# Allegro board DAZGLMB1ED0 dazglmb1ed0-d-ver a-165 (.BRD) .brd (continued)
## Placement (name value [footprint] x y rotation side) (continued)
CN2078  P_TP@196195-10021  [196195-10021-10P-L]  137.5 50.53 0 top
CN2079  Tobii@50228-0067N-001  [87212-0600-6P-L]  31.6 85 90 top
D11  SDM20U30-7  [D-1_2X0_8-0_7H]  174.52 61.43 0 bottom
D13  *SDM20U30-7  [D-1_2X0_8-0_7H]  174.52 62.83 0 bottom
D15  *SDM20U30-7  [D-1_2X0_8-0_7H]  174.52 60.04 0 bottom
D17  *SDM20U30-7  [D-1_2X0_8-0_7H]  174.52 65.62 0 bottom
D18  *SDM20U30-7  [D-1_2X0_8-0_7H]  174.52 64.23 0 bottom
D19  RB500V-40  [DSM]  175.75 64.86 270 top
D51  AZ5725-01F.R7G  [ESD-1X0_6-2P]  369.46 37.81 180 top
D73  *RB500V-40  [DSM]  342.29 64.61 90 top
D8553  *AZ5725-01F.R7G  [ESD-1X0_6-2P]  352.6 78.2 270 top
D8554  *AZ5725-01F.R7G  [ESD-1X0_6-2P]  353.61 78.2 270 top
D8555  *AZ5725-01F.R7G  [ESD-1X0_6-2P]  351.58 78.2 270 top
D8556  *AZ5725-01F.R7G  [ESD-1X0_6-2P]  350.57 78.2 270 top
D8557  SDM20U30-7  [D-1_2X0_8-0_7H]  348.51 90.26 90 bottom
D8558  *AZ5725-01F.R7G  [ESD-1X0_6-2P]  234.97 167.35 90 top
D8559  BAT54AW-L  [SOT323_213-2_1-1_3-3P]  228.37 165.57 90 top
D8565  *P_PB@AZ5725-01F.R7G  [ESD-1X0_6-2P]  172.87 58.64 90 top
D8566  *M_KB@AZ5725-01F.R7G  [ESD-1X0_6-2P]  127.53 53.94 270 bottom
D8567  *M_KB@AZ5725-01F.R7G  [ESD-1X0_6-2P]  127.53 55.97 90 bottom
D8568  BAT54CW  [UMT_213-3-1_3]  45.87 72.48 90 top
D8569  AZ5725-01F.R7G  [ESD-1X0_6-2P]  15.26 16.6 90 top
D8570  AZ5725-01F.R7G  [ESD-1X0_6-2P]  14.6 7.66 270 top
D8571  AZ5725-01F.R7G  [ESD-1X0_6-2P]  15.18 9.74 270 top
D8575  AZ5725-01F.R7G  [ESD-1X0_6-2P]  15.77 20.54 270 top
D8576  AZ5725-01F.R7G  [ESD-1X0_6-2P]  18.21 21.78 270 top
D8577  AZ5725-01F.R7G  [ESD-1X0_6-2P]  22.09 26.94 90 top
D8586  *RB500V-40  [DSM]  37.49 53.43 180 top
D8587  RB500V-40  [DSM]  37.49 51.53 180 top
D8588  SDM20U30-7  [D-1_2X0_8-0_7H]  135.28 119.6 180 bottom
D8589  RB500V-40  [DSM]  134.64 121.38 0 top
D8591  SDM20U30-7  [D-1_2X0_8-0_7H]  119.78 117.06 180 bottom
D8592  SDM20U30-7  [D-1_2X0_8-0_7H]  115.84 118.58 0 bottom
D8594  60@SDM20U30-7  [D-1_2X0_8-0_7H]  119.78 118.58 0 bottom
D8595  BAT54AW-L  [SOT323_213-2_1-1_3-3P]  122.83 119.35 0 top
D8596  AZ5725-01F.R7G  [ESD-1X0_6-2P]  25.67 73.96 270 top
D8597  AZ5725-01F.R7G  [ESD-1X0_6-2P]  25.67 75.96 90 top
D8598  AZ5725-01F.R7G  [ESD-1X0_6-2P]  17.93 36.54 180 top
D8599  PESD5V0H1BSF  [D-0_6X0_3-0_32H-SMT]  373.07 40.82 90 top
D13025  PESD5V0H1BSF  [D-0_6X0_3-0_32H-SMT]  367.75 47.65 270 bottom
D13026  PESD5V0H1BSF  [D-0_6X0_3-0_32H-SMT]  373.07 40.82 90 bottom
D13027  PESD5V0H1BSF  [D-0_6X0_3-0_32H-SMT]  367.75 47.65 270 top
D13028  PESD5V0H1BSF  [D-0_6X0_3-0_32H-SMT]  367.75 46.03 90 bottom
D13029  PESD5V0H1BSF  [D-0_6X0_3-0_32H-SMT]  373.07 42.44 270 top
D13030  PESD5V0H1BSF  [D-0_6X0_3-0_32H-SMT]  367.75 46.03 90 top
D13031  PESD5V0H1BSF  [D-0_6X0_3-0_32H-SMT]  373.07 42.44 270 bottom
D13032  PESD5V0H1BSF  [D-0_6X0_3-0_32H-SMT]  376.96 38.83 90 bottom
D13033  PESD5V0H1BSF  [D-0_6X0_3-0_32H-SMT]  378.1 38.83 90 bottom
D13034  PESD5V0H1BSF  [D-0_6X0_3-0_32H-SMT]  377.34 42.76 0 bottom
D13035  PESD5V0H1BSF  [D-0_6X0_3-0_32H-SMT]  382.8 43.91 180 bottom
D13036  PESD5V0H1BSF  [D-0_6X0_3-0_32H-SMT]  372.38 38.83 90 bottom
D13037  PESD5V0H1BSF  [D-0_6X0_3-0_32H-SMT]  373.53 38.83 90 bottom
D13038  RB500V-40  [DSM]  17.17 33.37 90 top
D13039  RB500V-40  [DSM]  18.94 33.37 90 top
D13040  *AZ5725-01F.R7G  [ESD-1X0_6-2P]  349.52 78.2 270 top
D13041  *AZ5725-01F.R7G  [ESD-1X0_6-2P]  348.48 78.17 270 top
D13042  *M_PB@AZ5725-01F.R7G  [ESD-1X0_6-2P]  377.01 15.79 90 bottom
D13046  *AZ5725-01F.R7G  [ESD-1X0_6-2P]  377.64 19.12 270 bottom
D13047  *AZ5725-01F.R7G  [ESD-1X0_6-2P]  375.81 19.52 0 bottom
D13048  *AZ5725-01F.R7G  [ESD-1X0_6-2P]  378.66 19.12 270 bottom
D13049  *AZ5725-01F.R7G  [ESD-1X0_6-2P]  369.59 21.43 270 bottom
D13050  *AZ5725-01F.R7G  [ESD-1X0_6-2P]  371.5 21.17 270 bottom
D13051  *AZ5725-01F.R7G  [ESD-1X0_6-2P]  372.51 21.17 270 bottom
D13053  *M_PB@AZ5725-01F.R7G  [ESD-1X0_6-2P]  379.7 10.56 270 top
D13054  *P_PB@AZ5725-01F.R7G  [ESD-1X0_6-2P]  180.5 48.93 180 top
D13055  *P_PB@AZ5725-01F.R7G  [ESD-1X0_6-2P]  181.03 46.6 180 top
D13056  *P_PB@AZ5725-01F.R7G  [ESD-1X0_6-2P]  180.52 47.74 180 top
D13057  *AZ5725-01F.R7G  [ESD-1X0_6-2P]  84.42 77.11 270 bottom
D13058  *AZ5725-01F.R7G  [ESD-1X0_6-2P]  86.76 77.11 270 bottom
D13059  *AZ5725-01F.R7G  [ESD-1X0_6-2P]  85.59 77.11 270 bottom
D13060  PESD5V0H1BSF  [D-0_6X0_3-0_32H-SMT]  375.81 38.83 90 bottom
D13061  PESD5V0H1BSF  [D-0_6X0_3-0_32H-SMT]  374.67 38.83 90 bottom
D13064  *Tobii@AZ5725-01F.R7G  [ESD-1X0_6-2P]  29.1 79.85 180 top
D13065  *Tobii@AZ5725-01F.R7G  [ESD-1X0_6-2P]  31.01 79.85 0 top
D13066  SUB@RB500V-40  [DSM]  37.49 49.7 180 top
D13067  *SUB@RB500V-40  [DSM]  37.49 47.9 180 top
D13069  RB500V-40  [DSM]  206.54 103.5 90 top
D13070  *RB500V-40  [DSM]  359.63 40.28 0 top
D13071  Debug@PESD5V0H1BSF  [D-0_6X0_3-0_32H-SMT]  217.95 170.15 270 top
D13072  Debug@PESD5V0H1BSF  [D-0_6X0_3-0_32H-SMT]  219.1 170.15 270 top
D13073  Debug@PESD5V0H1BSF  [D-0_6X0_3-0_32H-SMT]  220.24 170.15 270 top
D13074  Debug@PESD5V0H1BSF  [D-0_6X0_3-0_32H-SMT]  221.51 170.15 270 top
D13075  Debug@PESD5V0H1BSF  [D-0_6X0_3-0_32H-SMT]  222.91 170.15 270 top
D13076  Debug@PESD5V0H1BSF  [D-0_6X0_3-0_32H-SMT]  224.18 170.15 270 top
D13077  Debug@PESD5V0H1BSF  [D-0_6X0_3-0_32H-SMT]  225.42 170.15 270 top
D13078  Debug@PESD5V0H1BSF  [D-0_6X0_3-0_32H-SMT]  226.46 170.15 270 top
D13079  Debug@PESD5V0H1BSF  [D-0_6X0_3-0_32H-SMT]  240.56 169.26 270 top
D13080  Debug@PESD5V0H1BSF  [D-0_6X0_3-0_32H-SMT]  241.7 169.26 270 top
D13081  Debug@PESD5V0H1BSF  [D-0_6X0_3-0_32H-SMT]  243.25 169.26 270 top
D13082  Debug@PESD5V0H1BSF  [D-0_6X0_3-0_32H-SMT]  244.37 169.26 270 top
D13083  Debug@PESD5V0H1BSF  [D-0_6X0_3-0_32H-SMT]  245.61 169.23 270 top
D13084  Debug@PESD5V0H1BSF  [D-0_6X0_3-0_32H-SMT]  246.78 169.26 270 top
D13085  Debug@PESD5V0H1BSF  [D-0_6X0_3-0_32H-SMT]  247.82 169.26 270 top
D13086  Debug@PESD5V0H1BSF  [D-0_6X0_3-0_32H-SMT]  248.94 169.26 270 top
D13087  AZ5725-01F.R7G  [ESD-1X0_6-2P]  182.8 67.58 90 bottom
D13088  *SDM20U30-7  [D-1_2X0_8-0_7H]  124.73 108.8 0 bottom
D13089  SDM20U30-7  [D-1_2X0_8-0_7H]  14.41 29.15 270 bottom
D13090  SDM20U30-7  [D-1_2X0_8-0_7H]  16.06 22.19 270 bottom
D13094  AZ5725-01F.R7G  [ESD-1X0_6-2P]  24.51 80.23 270 top
D13095  *SDM20U30-7  [D-1_2X0_8-0_7H]  129.89 111.98 90 top
ESD7  Debug@AZ1045-04F.R7G  [UDFN10-2_5X1-5-9P]  229.13 169.89 180 top
ESD8  Debug@AZ1045-04F.R7G  [UDFN10-2_5X1-5-9P]  251.61 167.1 0 top
HOLE1  MBZ8P00301  [H-C197D126P2]  26.93 65 0 top
HOLE2  *H-C315D177P2  [H-C315D177P2]  100.84 92.19 0 top
HOLE3  *H-C315D126P2  [H-C315D126P2]  5 92.5 0 top
HOLE4  *H-C315D177P2  [H-C315D177P2]  19.5 57 0 top
HOLE5  *H-C315D177P2  [H-C315D177P2]  53 25.89 0 top
HOLE6  *H-C315D126P2  [H-C315D126P2]  200.5 61 0 top
HOLE7  *H-C315D126P2  [H-C315D126P2]  382 92.5 0 top
HOLE8  *H-C315D177P2  [H-C315D177P2]  210.5 176.5 0 top
HOLE9  *H-C315D118P2  [H-C315D118P2]  382 0.5 0 top
HOLE10  *H-C315D118P2  [H-C315D118P2]  5 0.5 0 top
HOLE11  *H-C315D162P2  [H-C315D162P2]  374 49 0 top
HOLE12  *H-C315D177P2  [H-C315D177P2]  288.64 91.82 0 top
HOLE13  *H-C315D126P2  [H-C315D126P2]  261.5 178 0 top
HOLE14  *H-TBC315IC126D126P2  [H-TBC315IC126D126P2]  119 178 0 top
HOLE15  *H-O152X112D152X112N  [H-O152X112D152X112N]  11.99 92.5 0 top
HOLE16  *H-TIC197BC315D150P2  [H-TIC197BC315D150P2]  184.58 104.73 0 top
HOLE17  *H-TIC197BC315D150P2  [H-TIC197BC315D150P2]  217.98 106.87 0 top
HOLE18  *H-TIC197BC315D150P2  [H-TIC197BC315D150P2]  161.11 159.05 0 top
HOLE19  *H-TIC197BC315D150P2  [H-TIC197BC315D150P2]  137.64 104.73 0 top
HOLE20  *H-TIC197BC315D150P2  [H-TIC197BC315D150P2]  217.98 131.59 0 top
HOLE21  *H-TIC197BC315D150P2  [H-TIC197BC315D150P2]  271.98 119.23 0 top
HOLE22  *H-O152X112D152X112N  [H-O152X112D152X112N]  11.52 3.5 0 top
JP1  *solderjumper-2  [SOLDERJUMPER-2]  325.27 51.4 180 top
JP10  *short3720  [SHORT3720]  98.83 76.24 0 top
L12  0.68uH_2.5x2.0x1.2  [L2_5X2-PHT25201T-R47MS]  355.34 62.2 90 top
L13  BLM15AG121SN1D  [R0402]  190.85 56.94 180 bottom
L14  BLM15AG121SN1D  [R0402]  190.82 58.28 180 bottom
L4234  SUB@0_5%_6  [R0603]  38.02 41.01 90 bottom
L4235  SUB@0_5%_6  [R0603]  39.69 42.28 90 bottom
L4236  SUB@0_5%_6  [R0603]  28.32 37.48 180 top
L4237  SUB@0_5%_6  [R0603]  28.34 39.31 180 top
L4238  BLM15AG121SN1D  [R0402]  179.85 69.94 270 top
L4240  PBY160808T-600Y-N  [R0603]  32.51 25.77 270 top
L4241  HCB2012KF-220T60  [R0805]  20.98 33.24 90 top
L4242  4.7uH_3.2x2.5x2  [L3_2X2_5-3_2]  344.19 69.56 0 top
L4243  HCB1608KF-601T10  [R0603]  345.46 71.97 0 top
L4244  HCB1608KF-601T10  [R0603]  342.79 71.97 0 top
L4245  PBY160808T-600Y-N  [R0603]  163.6 102.71 0 top
L4246  PBY160808T-600Y-N  [R0603]  153.18 105.76 270 bottom
L4247  *MCM2012B900GBE  [FILTER-MCM2012B900GBE-4P]  21.18 39.72 0 top
L4248  *MCM2012B900GBE  [FILTER-MCM2012B900GBE-4P]  21.36 37.43 0 top
L4249  *MCM2012B900GBE  [FILTER-MCM2012B900GBE-4P]  21.36 42 0 top
L4250  BLM15PX330SN1D  [R0402]  30.12 56.18 0 top
L4251  *MCM2012B900GBE  [FILTER-MCM2012B900GBE-4P]  21.36 48.73 0 top
L4252  *MCM2012B900GBE  [FILTER-MCM2012B900GBE-4P]  21.36 46.57 0 top
L4253  *MCM2012B900GBE  [FILTER-MCM2012B900GBE-4P]  21.36 50.89 0 top
L4254  *MCM2012B900GBE  [FILTER-MCM2012B900GBE-4P]  28.09 74.9 0 top
L4255  *MCM2012B900GBE  [FILTER-MCM2012B900GBE-4P]  366.42 59.4 180 top
L4256  *MCM2012B900GBE  [FILTER-MCM2012B900GBE-4P]  366.42 61.43 180 top
L4257  *MCM2012B900GBE  [FILTER-MCM2012B900GBE-4P]  366.42 57.37 180 top
L4258  PBY160808T-600Y-N  [R0603]  330.22 62.6 90 top
L4259  *PBY160808T-600Y-N  [R0603]  331.69 62.6 90 top
L4264  *PBY160808T-600Y-N  [R0603]  334.28 62.96 0 top
L4266  1uH_0.7A_0603  [R0603]  338.73 48.73 0 top
L4268  DIS@BLM15PX330SN1D  [R0402]  331.67 68.29 90 bottom
L4269  PBY160808T-600Y-N  [R0603]  37.87 31.72 270 top
L4270  BLM15PX330SN1D  [R0402]  30.75 30.88 270 bottom
L4271  *BLM15PX330SN1D  [R0402]  24.18 19.12 0 bottom
L4272  SUB@HCB2012KF-220T60  [R0805]  28.44 42.61 270 top
L4273  BLM15PX330SN1D  [R0402]  23.66 36.03 0 bottom
LED1  R/G/B_LTST-C19JZRGBW-Q  [LEDLTST-C19JZRGBW-Q-4P]  376.5 33.75 0 top
LED2  R/G/B_LTST-C19JZRGBW-Q  [LEDLTST-C19JZRGBW-Q-4P]  376.5 23.36 0 top
MR1  YB8251ST23  [SOT23_213-3_3-2]  235.5 162 90 top
NOREF  -  []  282.98 14.44 0 top
NOREF#2  -  [unnamed#2]  235.7 171.77 0 top
NOREF#3  -  []  19.53 91.15 0 top
NOREF#4  -  []  97.05 -1.81 0 top
NOREF#5  -  []  196.35 47.42 0 top
NOREF#6  -  [unnamed#2]  381.09 6.61 0 top
NOREF#7  -  [unnamed#2]  12.29 88.48 0 top
NOREF#8  -  []  113.86 94.64 180 bottom
NOREF#9  -  []  200.48 47.67 180 bottom
NOREF#10  -  [unnamed#2]  18.21 92.15 180 bottom
NOREF#11  -  [unnamed#2]  235.82 171.68 180 bottom
NOREF#12  -  [unnamed#2]  381.09 6.61 180 bottom
PC1  1000p/50V_4  [C0402]  207.79 169.33 90 bottom
PC2  0.047u/50V_6  [C0603]  209.06 168.88 270 bottom
PC3  0.1u/25V_4  [C0402]  73.91 61.26 180 bottom
PC4  0.1u/25V_4  [C0402]  72.28 61.92 90 bottom
PC5  0.1u/50V_6  [C0603]  192.68 167.22 0 top
PC6  0.1u/25V_4  [C0402]  73.91 62.22 180 bottom
PC7  2200p/50V_4  [C0402]  216.12 170.73 180 top
PC8  0.01u/50V_4  [C0402]  75.2 59.33 180 bottom
PC9  2.2u/10V_4  [C0402]  76.22 57.09 180 bottom
PC10  *47p/50V_4  [C0402]  152.39 57.75 180 bottom
PC11  *47p/50V_4  [C0402]  154.2 57.75 0 bottom
PC12  0.1u/50V_6  [C0603]  214.55 171.44 270 top
PC13  2200p/50V_4  [C0402]  190.9 171.29 0 top
PC14  0.1u/50V_6  [C0603]  189.89 172.56 0 top
PC15  0.047u/50V_4  [C0402]  76.6 54.32 180 bottom
PC16  0.47u/25V_4  [C0402]  76.6 52.8 180 bottom
PC17  *0.01u/50V_4  [C0402]  70.73 61.38 180 bottom
PC18  *100p/50V_4  [C0402]  65.4 53.41 270 bottom
PC19  *680p/50V_6  [C0603]  79.65 59.02 0 bottom
PC20  100p/50V_4  [C0402]  65.43 51.15 270 bottom
PC25  0.1u/50V_4  [C0402]  73.88 51.05 180 bottom
PC35  0.1u/50V_4  [C0402]  73.88 49.62 0 bottom
PC36  0.1u/50V_4  [C0402]  71.8 50.23 270 bottom
PC37  100p/50V_4  [C0402]  66.67 51.15 90 bottom
PC47  0.1u/16V_4  [C0402]  241.35 121.78 0 bottom
PC50  22u/6.3V_8  [C0805]  245.81 140.08 0 top
PC51  2200p/50V_4  [C0402]  112.16 66.64 270 top
PC62  *2200p/50V_4  [C0402]  214.75 162.4 90 top
PC81  *680p/50V_6  [C0603]  227.71 163.44 180 top
PC97  10u/6.3V_4  [C0402_2]  111.01 55.44 0 bottom
PC98  10u/6.3V_4  [C0402_2]  110.51 62.32 0 bottom
PC99  0.1u/16V_4  [C0402]  110.44 56.52 0 bottom
PC100  1000p/50V_4  [C0402]  112.6 58.56 180 bottom
PC101  1000p/50V_4  [C0402]  112.64 59.66 180 bottom
PC102  0.1u/16V_4  [C0402]  110.44 60.94 0 bottom
PC103  1u/25V_4  [C0402]  108.39 56.51 180 bottom
PC104  1u/25V_4  [C0402]  108.39 60.96 180 bottom
PC106  *0.1u/16V_4  [C0402]  106.19 57.7 0 bottom
PC107  *0.1u/16V_4  [C0402]  106.19 60.09 0 bottom
PC108  0.1u/16V_4  [C0402]  106.19 58.77 0 bottom
PC124  220u/6.3V_D6.3H4.2  [ECAP6_3X5_8-7_2]  68.65 62.96 135 top
PC125  0.1u/50V_4  [C0402]  98.37 57.27 90 bottom
PC126  0.1u/50V_4  [C0402]  70.29 67.14 180 bottom
PC127  220u/6.3V_D6.3H4.2  [ECAP6_3X5_8-7_2]  100.86 59.17 90 top
PC128  33u/25V_D6.3H4.5  [ECAP6_3X6_1-7_2]  84.96 66.31 270 top
PC129  1000p/50V_4  [C0402]  41.13 67.12 90 top
PC130  *680p/50V_6  [C0603]  95.37 73.42 0 top
PC131  *680p/50V_6  [C0603]  72.41 73.12 180 bottom
PC132  1000p/50V_4  [C0402]  40.12 67.12 90 top
PC133  10u/6.3V_6  [C0603]  44.47 69.43 270 top
PC134  10u/6.3V_6  [C0603]  38.16 68.57 270 top
PC135  2200p/50V_4  [C0402]  87.75 71.9 270 top
PC136  2200p/50V_4  [C0402]  74.25 63.82 0 top
PC137  0.1u/16V_4  [C0402]  43.07 68.93 270 top
PC138  0.1u/16V_4  [C0402]  40.58 65.52 180 top
PC139  10u/25V_8  [C0805]  75.28 61.85 0 top
PC140  10u/25V_8  [C0805]  92.17 65.75 180 top
PC141  10u/6.3V_4  [C0402_2]  82.37 77.66 270 bottom
PC142  0.1u/25V_4  [C0402]  81.07 77.23 270 bottom
PC143  1u/25V_4  [C0402]  43.04 70.68 90 top
PC144  1u/25V_4  [C0402]  38.34 70.8 90 top
PC145  0.1u/16V_4  [C0402]  40.58 76.19 270 bottom
PC146  *0.1u/16V_4  [C0402]  39.49 76.19 270 bottom
PC147  *0.1u/16V_4  [C0402]  41.65 76.19 270 bottom
PC148  0.1u/50V_4  [C0402]  85.87 72.48 180 bottom
PC149  0.1u/50V_4  [C0402]  76.8 73.19 0 bottom
PC151  4.7u/6.3V_4  [C0402_2]  81.55 68.04 90 bottom
PC161  15u/25V_7343H1.9  [CC7343]  226.36 152.19 180 top
PC164  22u/25V_8  [C0805]  93.75 46.6 90 top
PC165  2200p/50V_4  [C0402]  97.63 46.83 90 top
PC166  22u/25V_8  [C0805]  95.85 46.57 90 top
PC167  0.1u/50V_6  [C0603]  147.9 53.96 270 top
PC168  *100p/50V_4  [C0402]  166.9 57.73 0 top
PC170  10u/25V_8  [C0805]  76.14 57.5 270 top
PC172  2200p/50V_4  [C0402]  73.82 55.97 0 top
PC174  EV@1u/10V_4  [C0402]  131.67 66.74 270 bottom
PC182  EV@1u/10V_4  [C0402]  131.67 69.38 90 bottom
PC184  EV@1u/6.3V_2  [C0201]  126.61 62.81 270 bottom
PC217  0.1u/50V_6  [C0603]  220.75 152.49 90 top
PC219  330u/2V_7343H1.9  [CC7343]  217.77 159 90 top
PC220  2200p/50V_6  [C0603]  235.61 157.06 270 top
PC221  10u/25V_8  [C0805]  233.8 158.87 270 top
PC222  0.1u/50V_6  [C0603]  238.02 164.81 270 top
PC223  1u/10V_4  [C0402]  239.29 164.43 270 top
PC260  10u/6.3V_6  [C0603]  201.82 74.77 270 top
PC261  *10u/6.3V_6  [C0603]  196.11 71.82 90 top
PC262  0.1u/16V_4  [C0402]  200.53 74.34 270 top
PC263  0.47u/6.3V_4  [C0402]  193.92 72.53 270 top
PC264  4.7u/6.3V_6  [C0603]  194.86 77.66 180 top
PC2021  *0.1u/16V_4  [C0402]  175.43 81.8 0 bottom
PC2022  *0.1u/16V_4  [C0402]  175.43 79.87 0 bottom
PC2023  0.1u/25V_4  [C0402]  189.91 81.27 270 bottom
PC2024  10u/25V_8  [C0805]  180.08 78.15 90 top
PC2025  0.1u/25V_4  [C0402]  182.67 81.4 270 top
PC2026  10u/6.3V_4  [C0402_2]  180.11 76.65 90 bottom
PC2027  10u/25V_8  [C0805]  184.2 81.53 270 top
PC2028  2200p/50V_4  [C0402]  188.95 81.27 270 bottom
PC2029  0.1u/50V_4  [C0402]  183.51 82.13 180 bottom
PC2030  0.033u/16V_4  [C0402]  177.9 76.55 90 bottom
PC2031  0.1u/16V_4  [C0402]  197.4 91.36 270 top
PC2032  22u/6.3V_8  [C0805]  200.93 91.91 270 top
PC2033  *330u/2V_7343H1.9  [CC7343]  193.19 88.13 180 top
PC2034  0.1u/16V_4  [C0402]  175.94 76.55 270 bottom
PC2035  22u/6.3V_8  [C0805]  198.39 77.28 180 top
PC2036  22u/6.3V_8  [C0805]  202.92 91.91 270 top
PC2037  22u/6.3V_8  [C0805]  198.95 91.91 270 top
PC2038  *10u/6.3V_6  [C0603]  182.24 78.58 90 bottom
PC2039  *680p/50V_6  [C0603]  184.42 86.58 0 top
PC2040  1u/6.3V_2  [C0201]  180.36 83.91 90 bottom
PC5583  1u/6.3V_2  [C0201]  270.91 168.6 90 top
PC5584  4.7u/6.3V_4  [C0402_2]  263.29 163.54 180 bottom
PC5585  *0.1u/10V_2  [C0201]  261.39 167.48 90 top
PC5586  *0.1u/10V_2  [C0201]  268.24 160.49 90 bottom
PC5587  *330p/50V_4  [C0402]  261.34 161.81 90 top
PC5588  *0.1u/10V_2  [C0201]  268.55 157.78 180 top
PC5589  470p/50V_4  [C0402]  269.26 165.12 90 bottom
PC5590  68p/50V_4  [C0402]  271.98 164.99 0 bottom
PC5591  *0.1u/10V_2  [C0201]  262.28 168.47 90 top
PC5592  330p/50V_4  [C0402]  271.98 166.06 0 top
PC5593  1u/6.3V_2  [C0201]  263.24 161.46 0 bottom
PC5594  *0.1u/10V_2  [C0201]  271.83 158.69 180 top
PC5595  10u/25V_6  [C0603]  241.19 155.62 180 bottom
PC5596  10u/25V_6  [C0603]  241.35 157.88 180 top
PC5598  2200p/50V_4  [C0402]  241.22 154.4 180 bottom
PC5600  1u/6.3V_2  [C0201]  236.98 154.68 90 top
PC5601  10u/25V_6  [C0603]  241.35 157.88 180 bottom
PC5602  1u/25V_4  [C0402]  236.88 151.96 0 top
PC5603  0.1u/25V_4  [C0402]  223.72 151.98 0 bottom
PC5605  1u/25V_4  [C0402]  236.6 153.31 90 top
PC5606  *2200p/50V_4  [C0402]  241.55 153 270 bottom
PC5608  1u/6.3V_2  [C0201]  244.34 154.37 90 top
PC5614  1u/25V_4  [C0402]  243.58 152.37 90 top
PC5616  *2200p/50V_4  [C0402]  248.61 153.13 270 bottom
PC5623  1u/6.3V_2  [C0201]  251.51 154.37 90 top
PC5624  1u/25V_4  [C0402]  250.87 152.39 90 top
PC5626  *2200p/50V_4  [C0402]  256 153.03 270 bottom
PC5634  1u/6.3V_2  [C0201]  266.09 152.01 90 top
PC5635  1u/25V_4  [C0402]  265.81 149.78 90 top
PC5638  *2200p/50V_4  [C0402]  270.68 150.46 270 bottom
PC5639  1u/6.3V_2  [C0201]  258.82 151.76 90 top
PC5646  1u/25V_4  [C0402]  258.41 149.78 90 top
PC5647  *2200p/50V_4  [C0402]  263.7 150.46 270 bottom
PC5653  1u/6.3V_2  [C0201]  228.06 148.68 0 top
PC5654  1u/25V_4  [C0402]  226.26 149.34 0 top
PC5660  *2200p/50V_4  [C0402]  228.01 144.75 180 bottom
PC5667  0.1u/10V_2  [C0201]  265.83 168.47 270 bottom
PC6228  0.1u/16V_4  [C0402]  287.78 86.16 180 top
PC8099  VL@10u/25V_8  [C0805]  361.15 92.74 270 top
PC8100  VL@10u/25V_8  [C0805]  359.42 89.87 0 top
PC8101  VL@820p/50V_4  [C0402]  363.17 84.9 90 top
PC8102  VL@0.1u/25V_4  [C0402]  368.91 85.35 90 top
PC8103  VL@1u/25V_4  [C0402]  361.68 89.9 90 top
PC8104  VL@0.1u/25V_4  [C0402]  363.14 86.68 270 top
PC8105  VL@10u/25V_8  [C0805]  374.71 91.22 180 top
PC8106  VL@10u/25V_8  [C0805]  372.04 92.72 270 top
PC8107  VL@10u/25V_8  [C0805]  374.71 93.21 180 top
PC8108  VL@10u/25V_8  [C0805]  369.45 87.67 0 top
PC8109  *VL@0.1u/25V_4  [C0402]  355.42 92.57 270 top
PC9000  EV@0.1u/16V_4  [C0402]  148.48 66.64 180 bottom
PC9001  EV@0.022u/25V_4  [C0402]  139.97 62.55 180 bottom
PC9002  EV@820p/50V_4  [C0402]  148.48 73.32 270 top
PC9003  *EV@0.015u/25V_4  [C0402]  137.54 68.85 180 bottom
PC9004  *EV@0.1u/16V_4  [C0402]  137.54 69.82 0 bottom
PC9005  *EV@0.1u/16V_4  [C0402]  136.19 69.43 270 bottom
PC9006  *EV@0.015u/25V_4  [C0402]  136.19 67.45 270 bottom
PC9007  EV@4700p/50V_4  [C0402]  139.47 75.2 270 bottom
PC9008  EV@0.047u/25V_4  [C0402]  136.72 64.61 270 bottom
PC9009  *EV@1000p/50V_4  [C0402]  138.07 64.99 0 bottom
PC9010  *EV@1000p/50V_4  [C0402]  139.97 63.52 180 bottom
PC9011  EV@0.1u/25V_4  [C0402]  142.9 63.19 180 top
PC9012  EV@1u/10V_4  [C0402]  141.85 72.84 180 bottom
PC9013  *EV@1500p/50V_4  [C0402]  140.43 75.2 270 bottom
PC9014  *EV@1000p/50V_4  [C0402]  142.44 64.58 90 bottom
PC9015  EV@0.12u/10V_4  [C0402]  148.05 65.19 270 bottom
PC9016  *EV@1000p/50V_4  [C0402]  146.71 64.81 180 bottom
PC9017  EV@1u/6.3V_2  [C0201]  146.71 70.6 0 bottom
PC9018  EV@4.7u/25V_8  [C0805]  130.12 90.57 0 top
PC9022  EV@0.1u/25V_4  [C0402]  133.52 88.79 180 bottom
PC9023  EV@2200p/50V_4  [C0402]  133.55 90.77 0 bottom
PC9025  EV@15u/25V_7343H1.9  [CC7343]  123.79 71.9 270 top
PC9026  EV@4.7u/6.3V_4  [C0402_2]  134.77 98.9 90 top
PC9027  EV@0.22u/25V_6  [C0603]  129.69 92.27 180 top
PC9029  EV@220u/2.5V_D5H3.9  [ECAP5X3_8-6]  155.09 96.49 270 top
PC9030  *EV@2200p/50V_4  [C0402]  139.57 89.98 270 bottom
PC9063  EV@1u/25V_4  [C0402]  107.08 71.47 90 top
PC9064  EV@1u/25V_4  [C0402]  102.2 71.59 0 top
PC9065  EV@10u/6.3V_6  [C0603]  107.34 69.23 270 top
PC9066  EV@0.1u/16V_4  [C0402]  106.42 67.02 90 top
PC9067  EV@0.1u/16V_4  [C0402]  103.53 67.02 90 top
PC9068  EV@10u/6.3V_6  [C0603]  102.43 69.46 270 top
PC9069  EV@0.1u/16V_4  [C0402]  104.67 72.99 270 top
PC9070  *EV@820p/50V_4  [C0402]  105.68 72.99 270 top
PC9071  *EV@0.1u/16V_4  [C0402]  103.65 72.99 270 top
PC9072  *EV@1000p/50V_4  [C0402]  105.46 67.02 90 top
PC9073  *EV@1000p/50V_4  [C0402]  104.49 67.02 90 top
PC9074  EV@0.1u/16V_4  [C0402]  164.51 64.08 270 top
PC9075  EV@10u/6.3V_6  [C0603]  164.56 60.52 90 top
PC9076  EV@10u/6.3V_6  [C0603]  155.63 60.81 90 top
PC9077  EV@10u/6.3V_6  [C0603]  157.07 60.8 90 top
PC9078  EV@0.1u/16V_4  [C0402]  158.39 61.23 90 top
PC9079  *EV@220u/2V_7343H1.9  [CC7343]  148.86 64.61 180 top
PC9080  EV@0.01u/50V_4  [C0402]  161.11 60.6 0 bottom
PC9081  *EV@0.1u/16V_4  [C0402]  163.82 59.5 270 bottom
PC9082  EV@0.1u/16V_4  [C0402]  159.3 59.63 90 bottom
PC9101  EV@2.2u/10V_4  [C0402]  115.34 80.28 270 top
PC9102  EV@10u/25V_8  [C0805]  109.04 80.64 180 top
PC9103  EV@10u/25V_8  [C0805]  109.04 78.66 180 top
PC9106  EV@0.1u/25V_4  [C0402]  108.4 80.81 180 bottom
PC9107  EV@2200p/50V_4  [C0402]  108.4 79.77 180 bottom
PC9109  EV@0.22u/25V_6  [C0603]  112.85 79.42 90 top
PC9110  EV@330u/2V_7343H1.9  [CC7343]  124.05 95.32 270 top
PC9112  *EV@0.047u/16V_4  [C0402]  111.25 75.61 0 top
PC9113  *EV@2200p/50V_4  [C0402]  109.47 85.26 90 bottom
PC9121  EV@0.1u/16V_4  [C0402]  115.13 72.36 90 top
PC9124  *EV@56p/50V_4  [C0402]  119.96 75.81 270 top
PC9126  EV@100p/50V_4  [C0402]  113.15 73.7 0 top
PC9127  *EV@100p/50V_4  [C0402]  118.99 74.08 270 top
PC9128  *EV@56p/50V_4  [C0402]  118.03 72.36 90 top
PC9129  *EV@56p/50V_4  [C0402]  120.34 72.51 180 top
PC9131  *EV@0.1u/25V_4  [C0402]  116.1 72.36 90 top
PC9186  EV@1u/25V_6  [C0603]  118.1 70.07 90 top
PC9194  EV@0.1u/25V_4  [C0402]  108.4 78.81 180 bottom
PC9305  EV@330u/2V_7343H1.9  [CC7343]  115.18 102.66 180 top
PC9324  *EV@22u/6.3V_8  [C0805]  121.99 105.63 180 top
PC9325  *EV@22u/6.3V_8  [C0805]  113.3 106.14 0 top
PC9326  EV@22u/6.3V_8  [C0805]  121.99 103.62 180 top
PC9354  330u/2V_7343H1.9  [CC7343]  237.51 136.23 180 top
PC9374  22u/6.3V_6  [C0603]  95.85 76.7 90 top
PC9375  *2200p/50V_4  [C0402]  93.97 82.16 90 bottom
PC9376  *68p/50V_4  [C0402]  89.28 77.97 90 top
PC9377  10u/6.3V_6  [C0603]  92.91 77.44 90 top
PC9378  *22p/50V_4  [C0402]  88.26 79.7 270 top
PC9379  1u/6.3V_2  [C0201]  90.29 77.84 270 top
PC9380  0.1u/25V_4  [C0402]  95.73 76.72 90 bottom
PC9381  *0.1u/16V_4  [C0402]  89.1 82.01 0 top
PC9382  0.01u/50V_4  [C0402]  94.13 77.94 90 top
PC9383  1000p/50V_2  [C0201]  270.12 168.98 90 bottom
PC9384  22u/6.3V_8  [C0805]  234.36 144.54 0 top
PC9385  22u/6.3V_8  [C0805]  234.41 146.55 0 top
PC9386  0.1u/16V_4  [C0402]  241.32 120.77 0 bottom
PC9387  330u/2V_7343H1.9  [CC7343]  252.35 140.97 0 top
PC9388  22u/6.3V_8  [C0805]  242.2 142.09 180 top
PC9389  22u/6.3V_8  [C0805]  242.2 140.08 180 top
PC9390  0.1u/16V_4  [C0402]  241.32 119.73 0 bottom
PC9391  330u/2V_7343H1.9  [CC7343]  235.33 140.98 180 top
PC9392  10u/25V_6  [C0603]  248.64 157.88 180 bottom
PC9393  0.1u/25V_4  [C0402]  248.18 154.52 180 bottom
PC9394  10u/25V_6  [C0603]  248.64 157.88 180 top
PC9395  1u/25V_4  [C0402]  244.55 152.37 90 top
PC9396  10u/25V_6  [C0603]  248.23 155.77 180 bottom
PC9397  2200p/50V_4  [C0402]  244.77 149.78 0 bottom
PC9398  10u/25V_6  [C0603]  256.23 157.88 180 top
PC9399  0.1u/25V_4  [C0402]  256.2 156.02 180 bottom
PC9400  10u/25V_6  [C0603]  256.13 154.75 180 bottom
PC9401  1u/25V_4  [C0402]  251.84 152.39 90 top
PC9402  10u/25V_6  [C0603]  256.23 157.88 180 bottom
PC9403  2200p/50V_4  [C0402]  255.85 148.3 180 bottom
PC9404  10u/25V_6  [C0603]  270.68 155.41 180 bottom
PC9405  1u/25V_4  [C0402]  266.77 149.78 90 top
PC9406  10u/25V_6  [C0603]  270.15 153.36 180 bottom
PC9407  10u/25V_6  [C0603]  270.68 155.41 180 top
PC9409  2200p/50V_4  [C0402]  270.12 152.14 180 bottom
PC9410  0.1u/25V_4  [C0402]  223.72 150.99 0 bottom
PC9411  22u/6.3V_8  [C0805]  267.1 135.68 180 top
PC9412  22u/6.3V_8  [C0805]  267.1 137.71 180 top
PC9413  0.1u/16V_4  [C0402]  272.86 141.03 180 top
PC9414  330u/2V_7343H1.9  [CC7343]  254.23 136.21 180 top
PC9415  10u/25V_6  [C0603]  263.19 155.44 180 bottom
PC9416  10u/25V_6  [C0603]  263.19 155.43 180 top
PC9417  0.1u/25V_4  [C0402]  262.94 152.77 180 bottom
PC9418  10u/25V_6  [C0603]  262.76 153.97 180 bottom
PC9419  1u/25V_4  [C0402]  259.38 149.78 90 top
PC9420  2200p/50V_4  [C0402]  262.94 151.81 180 bottom
PC9421  22u/6.3V_8  [C0805]  268.64 139.72 180 top
PC9422  22u/6.3V_8  [C0805]  258.84 139.68 0 top
PC9423  0.1u/16V_4  [C0402]  258.04 141.55 90 top
PC9425  10u/25V_6  [C0603]  232.02 145.25 90 bottom
PC9426  1u/25V_4  [C0402]  226.26 148.38 0 top
PC9427  10u/25V_6  [C0603]  232.02 145.25 90 top
PC9428  2200p/50V_4  [C0402]  229.38 145.1 90 bottom
PC9429  0.1u/25V_4  [C0402]  229.23 155.13 180 top
PC9430  22u/6.3V_8  [C0805]  230.93 136.75 180 top
PC9431  22u/6.3V_8  [C0805]  228.9 142.69 180 top
PC9432  22u/6.3V_8  [C0805]  228.9 138.73 180 top
PC9433  22u/6.3V_8  [C0805]  228.9 140.71 180 top
PC9435  22u/6.3V_8  [C0805]  225.1 138.3 0 top
PC9436  EV@10u/25V_8  [C0805]  121.31 83.76 0 top
PC9438  EV@10u/25V_8  [C0805]  121.31 81.78 0 top
PC9439  *EV@2200p/50V_4  [C0402]  118.71 87.72 0 bottom
PC9440  EV@0.1u/25V_4  [C0402]  122.32 82.21 0 bottom
PC9441  EV@2200p/50V_4  [C0402]  122.32 83.18 0 bottom
PC9442  EV@0.1u/25V_4  [C0402]  122.32 84.14 0 bottom
PC9443  EV@47u/6.3V_6  [C0603]  114.85 112.77 0 top
PC9444  EV@330u/2V_7343H1.9  [CC7343]  118.13 165.9 180 top
PC9446  EV@330u/2V_7343H1.9  [CC7343]  118.1 161.1 180 top
PC9447  EV@0.22u/25V_6  [C0603]  117.95 79.37 90 top
PC9451  EV@4.7u/25V_8  [C0805]  134.18 90.62 180 top
PC9452  EV@4.7u/25V_8  [C0805]  130.12 88.59 0 top
PC9453  *EV@4.7u/25V_8  [C0805]  134.18 88.64 180 top
PC9454  EV@0.1u/25V_4  [C0402]  133.55 89.78 180 bottom
PC9455  EV@0.1u/25V_4  [C0402]  131.85 77.92 180 bottom
PC9456  EV@0.1u/25V_4  [C0402]  131.85 76.93 180 bottom
PC9457  EV@4.7u/25V_8  [C0805]  132.48 78.53 180 top
PC9458  EV@2200p/50V_4  [C0402]  131.85 78.91 0 bottom
PC9459  EV@4.7u/25V_8  [C0805]  132.48 76.55 180 top
PC9460  EV@4.7u/25V_8  [C0805]  132.48 72.58 180 top
PC9461  *EV@4.7u/25V_8  [C0805]  132.48 74.57 180 top
PC9462  EV@0.1u/25V_4  [C0402]  159.58 71.26 270 bottom
PC9463  EV@0.1u/25V_4  [C0402]  158.59 71.26 270 bottom
PC9464  EV@4.7u/25V_8  [C0805]  159.96 71.9 270 top
PC9465  EV@2200p/50V_4  [C0402]  157.6 71.26 90 bottom
PC9466  EV@4.7u/25V_8  [C0805]  157.98 71.9 270 top
PC9467  EV@4.7u/25V_8  [C0805]  157.96 68.34 90 top
PC9468  *EV@4.7u/25V_8  [C0805]  159.94 68.34 90 top
PC9469  EV@0.1u/25V_4  [C0402]  170.33 71.26 270 bottom
PC9470  EV@0.1u/25V_4  [C0402]  171.32 71.26 270 bottom
PC9471  EV@4.7u/25V_8  [C0805]  169.72 71.92 270 top
PC9472  EV@2200p/50V_4  [C0402]  169.34 71.26 90 bottom
PC9473  EV@4.7u/25V_8  [C0805]  171.7 71.92 270 top
PC9474  EV@4.7u/25V_8  [C0805]  169.72 68.19 90 top
PC9475  *EV@4.7u/25V_8  [C0805]  171.75 68.19 90 top
PC9477  EV@220u/2.5V_D5H3.9  [ECAP5X3_8-6]  166.9 96.49 270 top
PC9478  EV@330u/2V_7343H1.9  [CC7343]  198.6 105.86 0 top
PC9479  EV@220u/2.5V_D5H3.9  [ECAP5X3_8-6]  161.06 96.49 270 top
PC9480  EV@330u/2V_7343H1.9  [CC7343]  180.49 92.93 270 top
PC9481  EV@220u/2.5V_D5H3.9  [ECAP5X3_8-6]  172.74 96.49 270 top
PC9482  *EV@2200p/50V_4  [C0402]  137.46 78.38 270 bottom
PC9483  *EV@2200p/50V_4  [C0402]  157.6 77.36 0 bottom
PC9484  *EV@2200p/50V_4  [C0402]  168.4 76.14 0 bottom
PC9485  EV@0.22u/25V_6  [C0603]  127.22 80.43 180 top
PC9486  EV@0.22u/25V_6  [C0603]  155.85 67.5 270 top
PC9487  EV@0.22u/25V_6  [C0603]  167.69 67.5 270 top
PC9488  EV@4.7u/6.3V_4  [C0402_2]  131.82 86.38 0 top
PC9489  EV@4.7u/6.3V_4  [C0402_2]  150.11 72.03 90 top
PC9490  EV@4.7u/6.3V_4  [C0402_2]  161.89 71.95 90 top
PC9491  22u/6.3V_8  [C0805]  245.81 142.09 0 top
PC9492  *EV@47u/6.3V_6  [C0603]  114.85 114.85 0 top
PC9493  *EV@47u/6.3V_6  [C0603]  114.85 110.76 0 top
PC9494  *22u/25V_8  [C0805]  166.9 61.18 0 top
PC9495  *22u/25V_8  [C0805]  166.9 59.2 0 top
PC9496  33u/25V_D6.3H4.5  [ECAP6_3X6_1-7_2]  78.03 66.3 270 top
PD1  SV1040  [D-TO277_213-6_1X4_3]  200.81 166.08 90 top
PD2  P4SMAFJ20A  [D-3_8X2_5]  190.52 169.51 180 top
PD3  PDZ5.6B  [DSM]  62.81 55.69 270 top
PD4  PDZ5.6B  [DSM]  72.42 58.24 0 top
PD40  VL@DFLS240-7  [D-2_8X1_78]  369.94 92.04 90 top
PD101  EV@SDM20U30-7  [D-1_2X0_8-0_7H]  120.87 68.5 270 bottom
PD102  EV@SDM20U30-7  [D-1_2X0_8-0_7H]  119.35 68.5 270 bottom
PD9000  EV@RB500V-40  [DSM]  145.18 70.45 90 top
PD9003  EV@1SS355  [DSM]  146.07 55.63 90 top
PD9007  SV1040  [D-TO277_213-6_1X4_3]  196.36 166.08 90 top
PJ1  50458-00801-V02_Header  [50458-00801-V02-8P-L]  161.35 51.02 0 top
PJ2  JPD113D-DB570-7H  [DCJK-JPD113D-DB570-7H-5P]  198.5 177.4 180 top
PJ2003  *short3720  [SHORT3720]  200.27 87.72 90 top
PJ3004  *short3720  [SHORT3720]  233.57 153.89 180 top
PJ3005  *short3720  [SHORT3720]  217.62 151.91 0 top
PJ3007  *short3720  [SHORT3720]  199.03 71.37 0 top
PJ9002  *short3720  [SHORT3720]  123.67 78.88 180 top
PJ9003  *Short_0603  [S0603]  166.64 63.16 0 top
PJ9004  *short3720  [SHORT3720]  157.45 64 180 top
PJ9010  *short3720  [SHORT3720]  233.73 150.28 0 top
PJ9020  VL@0_5%_8  [R0805]  372.05 89.45 270 top
PJ9024  EV@0.005_1%_12  [R1206]  128.52 73.47 0 top
PJ9025  EV@0.005_1%_12  [R1206]  128.52 75.73 0 top
PJ9027  NVL@0_5%_8  [R0805]  371.21 89.41 270 bottom
PJ9028  *50458-01001-V02  [50458-01001-V02-10P-L]  161.35 51.02 0 top
PL1  1uH_7x7x3  [CHOKE-PCMC063T-3R3MN-SMT]  96.86 82.56 270 top
PL2  2.2uH_7x7x4  [L6_6X6_6-3_8]  97.51 68.06 270 top
PL3  2.2uH_7x7x3  [CHOKE-PCMC063T-3R3MN-SMT]  65.32 71.49 270 top
PL5  6.8uH_7x7x3  [CHOKE-PCMC063T-3R3MN-SMT]  85.95 57.96 0 top
PL6  0.33uH/20A_7x7x3  [CHOKE-PCMC063T-3R3MN-SMT]  223.24 144.24 270 top
PL9  VL@3.3uH_5x5x1.8  [L5_1X5_2-1_6H]  365.49 91.52 0 top
PL12  0.68uH_7x7x3  [CHOKE-PCMC063T-3R3MN-SMT]  223.82 159.05 270 top
PL15  2.2uH_2.5x2.0x1.2  [L2_5X2-1_2H]  198.11 74.59 0 top
PL2001  2.2uH_7x7x3  [CHOKE-PCMC063T-3R3MN-SMT]  193.94 82.19 0 top
PL8002  0.15uH/36A_7x7x4  [L6_6X6_6-3_8]  269.35 145.36 270 top
PL9001  EV@0.22H/35A_10x10x4  [L10X10-3_8]  144.93 92.45 0 top
PL9017  EV@0.22uH_7x7x4  [L6_6X6_6-3_8]  110.74 95.8 90 top
PL9019  0.15uH/36A_7x7x4  [L6_6X6_6-3_8]  262.16 145.36 270 top
PL9020  0.15uH/36A_7x7x4  [L6_6X6_6-3_8]  247.09 147.95 270 top
PL9021  0.15uH/36A_7x7x4  [L6_6X6_6-3_8]  239.8 147.92 270 top
PL9022  0.15uH/36A_7x7x4  [L6_6X6_6-3_8]  254.38 147.95 270 top
PL9023  EV@0.22uH_7x7x4  [L6_6X6_6-3_8]  118.1 95.8 90 top
PL9024  EV@0.22H/35A_10x10x4  [L10X10-3_8]  142.18 81.73 0 top
PL9025  EV@0.22H/35A_10x10x4  [L10X10-3_8]  156.2 82.39 90 top
PL9026  EV@0.22H/35A_10x10x4  [L10X10-3_8]  167 82.41 90 top
PQ1  AON6366E  [POWER-5_2X5_55-1_27-5P]  206.4 167.96 0 top
PQ2  AON6366E  [POWER-5_2X5_55-1_27-5P]  93.85 59.99 180 top
PQ6  2N7002K  [SOT23_213-3_3-2]  113.99 64.86 270 top
PQ8  LTC044EUBFS8TL  [UMT_213-3-1_3]  212.24 143.6 0 top
PQ9  PJA3404  [SOT23_213-3_3-2]  117.77 64.86 0 top
PQ12  *2N7002K  [SOT23_213-3_3-2]  35.63 64.63 90 top
PQ14  2N7002K  [SOT23_213-3_3-2]  30.5 71.59 0 top
PQ16  LTC044EUBFS8TL  [UMT_213-3-1_3]  34.06 71.06 0 top
PQ17  VL@AO3415  [SOT23_213-3_3-2]  358.23 92.78 180 top
PQ19  *2N7002K  [SOT23_213-3_3-2]  32.02 67.73 90 top
PQ21  AON6978  [POWER-5_2X5_55-1_27-7P]  91.18 70.78 0 top
PQ22  AON6978  [POWER-5_2X5_55-1_27-7P]  71.52 69.95 0 top
PQ29  AON7410  [DFN-8L-3X3-65-5P-0_9H]  79.42 59.16 180 top
PQ30  AON7410  [DFN-8L-3X3-65-5P-0_9H]  79.3 55.3 90 top
PQ40  *PJA3404  [SOT23_213-3_3-2]  203.09 69 270 top
PQ41  *2N7002K  [SOT23_213-3_3-2]  104.62 53.74 270 top
PQ147  EV@DMG1012T-7  [D-SOT523_213-1_6-1]  116.99 64.99 90 bottom
PQ9000  EV@DMG1012T-7  [D-SOT523_213-1_6-1]  146.86 73.37 0 top
PQ9001  EV@2N7002K  [SOT23_213-3_3-2]  141.78 74.44 0 top
PQ9009  EV@AON7408  [DFN-8L-3X3-65-5P-0_9H]  161.87 62.3 180 top
PQ9010  EV@2N7002K  [SOT23_213-3_3-2]  151.01 59.12 270 top
PQ9011  EV@DMG1012T-7  [D-SOT523_213-1_6-1]  147.73 56.42 270 top
PQ9013  EV@AON6414AL  [POWER-5_2X5_55-1_27-5P]  104.37 83.82 90 top
PQ9020  EV@METR3904-G  [SOT23_213-3_3-2]  110.74 69.36 180 top
PQ9021  EV@2N7002K  [SOT23_213-3_3-2]  115.51 69.28 270 top
PQ9031  EV@2N7002K  [SOT23_213-3_3-2]  102.89 78.58 90 top
PQ9032  EV@DMG1012T-7  [D-SOT523_213-1_6-1]  108.76 76.42 0 top
PQ9034  EV@2N7002K  [SOT23_213-3_3-2]  147.21 59.73 180 top
PQ9049  EV@AON6752  [POWER-5_2X5_55-1_27-5P]  110.04 87.74 270 top
PQ9050  2N7002K  [SOT23_213-3_3-2]  109.42 53.79 270 top
PQ9051  EV@AON6414AL  [POWER-5_2X5_55-1_27-5P]  123.18 87.57 180 top
PQ9052  EV@AON6752  [POWER-5_2X5_55-1_27-5P]  116.77 87.83 270 top
PQ9053  AON6978  [POWER-5_2X5_55-1_27-7P]  230.04 159.25 0 top
PQ9054  2N7002K  [SOT23_213-3_3-2]  212.39 159.6 180 top
PQ9055  PJA3404  [SOT23_213-3_3-2]  212.29 155.85 90 top
PQ9056  TPCA8064-H  [POWER-5X5-1_27-5P]  216.89 145.33 270 top
PQ9057  AON7410  [DFN-8L-3X3-65-5P-0_9H]  187.52 80.03 90 top
PQ9058  AON7752  [DFN-8L-3X3-65-5P-0_9H]  187.48 83.89 180 top
PQ9059  2N7002K  [SOT23_213-3_3-2]  212.24 148.53 270 top
PQ9080  VL@2N7002KTB  [SOT523_213-1_6-1-0_6H]  359.14 87.31 180 top
PQ9081  VL@LTC044EUBFS8TL  [UMT_213-3-1_3]  356.29 88.45 90 top
PQ9082  VL@2N7002K  [SOT23_213-3_3-2]  348.48 92.55 180 top
PQ9083  EV@LTC044EUBFS8TL  [UMT_213-3-1_3]  108.63 58.74 270 top
PQ9084  EV@2N7002KW  [UMT_213-3-1_3]  105 63.21 180 top
PQ9086  2N7002KW  [UMT_213-3-1_3]  65.4 47.77 90 top
PQ9087  PJA3411  [SOT23_213-3_3-2]  66.7 52.74 90 top
PQ9088  PJA3411  [SOT23_213-3_3-2]  65.64 56.46 90 top
PQ9089  2N7002KW  [UMT_213-3-1_3]  63.56 59.9 180 top
PR1  *Short_0201  [S0201]  212.06 167.61 90 top
PR2  *Short_0201  [S0201]  212.06 168.62 270 top
PR3  0.005_1%_3720  [RC3720-SMT]  212.03 168.14 180 top
PR4  *Short_0603  [S0603]  71.7 59.58 90 bottom
PR5  *Short_0402  [S0402]  73.86 59.91 270 bottom
PR6  *Short_0402  [S0402]  72.89 59.88 270 bottom
PR7  10_1%_6  [R0603]  70.28 59.58 90 bottom
PR8  *Short_0402  [S0402]  67.91 61.89 270 bottom
PR9  10K_5%_4  [R0402]  68.98 59.53 270 bottom
PR10  *0_5%_4  [R0402]  163.39 56.43 270 bottom
PR11  0_5%_6  [R0603]  76.6 55.85 0 bottom
PR12  100_5%_4  [R0402]  156.03 57.75 0 bottom
PR13  100_5%_4  [R0402]  152.39 56.79 0 bottom
PR14  100_5%_4  [R0402]  160.37 56.63 270 bottom
PR15  *10K_5%_4  [R0402]  66.95 59.53 270 bottom
PR16  20_5%_12  [R1206]  191.64 165.37 180 top
PR17  *Short_0402  [S0402]  66.64 57.55 90 bottom
PR18  1M_5%_4  [R0402]  161.51 56.63 90 bottom
PR19  *Short_0402  [S0402]  65.68 57.52 90 bottom
PR23  22.6K_1%_4  [R0402]  65.35 55.26 270 bottom
PR25  *Short_0402  [S0402]  66.75 53.53 180 bottom
PR26  *Short_0402  [S0402]  66.75 52.57 180 bottom
PR28  4.02K_1%_4  [R0402]  207.41 167.96 0 bottom
PR29  4.02K_1%_4  [R0402]  206.8 169.33 270 bottom
PR30  *Short_0402  [S0402]  70.56 51.65 270 bottom
PR31  866K_1%_4  [R0402]  69.57 51.64 270 bottom
PR32  *Short_0402  [S0402]  67.63 51.02 270 bottom
PR33  *4.7_5%_6  [R0603]  82.44 59.02 0 bottom
PR39  100K_1%_4  [R0402]  70.61 49.9 270 bottom
PR40  100K_1%_4  [R0402]  69.64 49.85 90 bottom
PR41  100_1%_4  [R0402]  268.14 168.85 270 bottom
PR43  *110_1%_4  [R0402]  267.18 168.85 270 bottom
PR44  45.3_1%_4  [R0402]  269.11 168.85 270 bottom
PR49  VL@100K_1%_4  [R0402]  354.4 92.57 270 top
PR51  VL@10K_5%_4  [R0402]  354.93 93.92 0 top
PR59  1M_5%_6  [R0603]  110.31 66.13 180 top
PR83  1M_5%_6  [R0603]  212.24 145.89 180 top
PR84  1M_5%_6  [R0603]  212.08 162.81 90 top
PR86  22_5%_8  [R0805]  212.24 151.45 180 top
PR97  100K_1%_4  [R0402]  89.05 82.97 180 top
PR98  20.5K_1%_4  [R0402]  88.26 77.94 90 top
PR100  *Short_0402  [S0402]  89.1 81.04 180 top
PR101  10K_1%_4  [R0402]  89.28 79.7 90 top
PR102  *Short_0402  [S0402]  91.08 83.94 0 top
PR104  *Short_0402  [S0402]  93.75 77.56 0 bottom
PR106  *22_5%_8  [R0805]  38.45 62.42 0 top
PR111  22_5%_8  [R0805]  27.58 71.09 270 top
PR112  *4.7_5%_6  [R0603]  225.04 164.3 180 top
PR114  *100K_1%_4  [R0402]  245.97 159.81 0 top
PR115  *0_5%_4  [R0402]  245.97 161.79 180 top
PR116  1M_5%_6  [R0603]  36.01 67.83 270 top
PR118  1M_5%_6  [R0603]  34.59 67.83 90 top
PR119  EV@10_1%_4  [R0402]  133.32 67.53 180 bottom
PR120  *100K_1%_6  [R0603]  36.47 70.7 270 top
PR124  *EV@665K_1%_4  [R0402]  133.32 65.6 180 bottom
PR126  *220_5%_8  [R0805]  32.71 64.25 270 top
PR127  *Short_0805  [S0805]  113.57 61.17 180 bottom
PR128  *Short_0805  [S0805]  111.3 53.11 270 bottom
PR130  *Short_0805  [S0805]  105.48 55.87 180 bottom
PR131  *Short_0402  [S0402]  104.16 57.47 0 bottom
PR132  *Short_0402  [S0402]  104.12 60.1 180 bottom
PR136  *Short_0402  [S0402]  104.11 58.81 0 bottom
PR138  *EV@665K_1%_4  [R0402]  133.32 68.57 180 bottom
PR139  EV@10_1%_4  [R0402]  133.32 69.54 180 bottom
PR146  EV@10_1%_4  [R0402]  133.32 70.5 180 bottom
PR161  *EV@10K_1%_4  [R0402]  123.08 68.93 180 bottom
PR167  *4.7_5%_6  [R0603]  98.01 73.42 0 top
PR168  *4.7_5%_6  [R0603]  69.74 73.12 180 bottom
PR169  *Short_0805  [S0805]  42.91 66.45 270 top
PR171  *Short_0603  [S0603]  79.8 77.66 90 bottom
PR172  *Short_0805  [S0805]  43.29 73.22 90 top
PR173  *Short_0805  [S0805]  37.96 73.72 90 top
PR174  *Short_0402  [S0402]  41.58 73.02 270 top
PR175  *Short_0402  [S0402]  40.57 73.02 270 top
PR176  *Short_0402  [S0402]  39.48 73.09 90 top
PR177  1_1%_6  [R0603]  85.87 74.01 0 bottom
PR178  1_1%_6  [R0603]  76.8 74.74 0 bottom
PR179  *Short_0402  [S0402]  85.49 71.16 0 bottom
PR180  *Short_0402  [S0402]  77.24 72 180 bottom
PR181  100K_1%_4  [R0402]  77.24 70.91 0 bottom
PR182  57.6K_1%_4  [R0402]  84.86 68.42 90 bottom
PR183  10K_5%_4  [R0402]  77.24 69.82 0 bottom
PR184  15.8K_1%_4  [R0402]  82.82 68.42 90 bottom
PR185  10K_1%_4  [R0402]  83.84 68.42 90 bottom
PR186  10K_1%_4  [R0402]  85.49 70.07 180 bottom
PR188  6.49K_1%_4  [R0402]  80.28 68.42 270 bottom
PR189  9.31K_1%_4  [R0402]  79.27 68.42 90 bottom
PR190  54.9K_1%_4  [R0402]  78.25 68.42 90 bottom
PR192  *Short_0603  [S0603]  78.87 71.91 180 top
PR204  316K_1%_4  [R0402]  75.33 61.69 270 bottom
PR205  *0_5%_4  [R0402]  67.97 59.53 270 bottom
PR206  100K_1%_4  [R0402]  75.2 60.29 0 bottom
PR207  100K_5%_4  [R0402]  67.61 57.55 270 bottom
PR208  *Short_0201  [S0201]  93.75 50.82 90 top
PR209  0.005_1%_2512  [RC2512-0_6H]  93.75 52.7 270 top
PR210  *Short_0201  [S0201]  93.75 54.58 270 top
PR211  137K_1%_4  [R0402]  68.61 51.64 270 bottom
PR255  *0_5%_6  [R0603]  211.88 153.23 0 top
PR263  100K_1%_4  [R0402]  243.89 159.58 0 top
PR264  *Short_0603  [S0603]  236.11 159.43 180 top
PR265  42.2K_1%_4  [R0402]  243.89 160.54 0 top
PR266  *Short_0402  [S0402]  245.97 160.82 0 top
PR267  10K_1%_4  [R0402]  243.89 161.54 180 top
PR268  470K_1%_4  [R0402]  240.69 163.29 180 top
PR287  *0_5%_6  [R0603]  65.96 63.9 180 bottom
PR298  *22_5%_8  [R0805]  107.03 55.69 0 top
PR303  *Short_0201  [S0201]  192.4 73.65 0 bottom
PR304  *Short_0402  [S0402]  189.68 72.99 0 top
PR305  *0_5%_4  [R0402]  191.08 72.66 90 top
PR306  10K_5%_4  [R0402]  192.55 72.94 0 top
PR307  47.5K_1%_4  [R0402]  190.16 74.16 0 top
PR308  15K_1%_4  [R0402]  190.14 75.15 0 top
PR309  *Short_0402  [S0402]  190.22 76.42 0 top
PR310  *Short_0603  [S0603]  192.22 77.66 180 top
PR311  100K_1%_4  [R0402]  188.46 76.39 180 top
PR312  *Short_0603  [S0603]  68.63 63.9 0 bottom
PR416  EV@10K_1%_4  [R0402]  117.75 68.04 90 bottom
PR417  EV@10K_1%_4  [R0402]  116.73 68.04 90 bottom
PR701  EV@10K_1%_4  [R0402]  123.85 64.74 270 bottom
PR702  EV@10K_1%_4  [R0402]  123.08 66.89 180 bottom
PR705  EV@10K_1%_4  [R0402]  114.83 66.13 270 bottom
PR706  *Short_0402  [S0402]  123.08 67.91 180 bottom
PR2016  100K_1%_4  [R0402]  176.63 84.27 90 bottom
PR2017  *Short_0402  [S0402]  177.59 84.27 270 bottom
PR2018  *Short_0402  [S0402]  175.43 82.77 0 bottom
PR2019  348K_1%_4  [R0402]  182.16 84.27 90 bottom
PR2020  *Short_0402  [S0402]  175.43 78.86 180 bottom
PR2021  499K_1%_4  [R0402]  175.66 84.27 90 bottom
PR2022  2.2_5%_6  [R0603]  183.51 80.69 0 bottom
PR2023  100_1%_4  [R0402]  176.93 76.55 270 bottom
PR2024  *Short_0402  [S0402]  181.2 84.27 90 bottom
PR2025  *4.7_5%_6  [R0603]  187.09 86.58 0 top
PR2026  *Short_0201  [S0201]  195.14 88.82 180 top
PR2027  *0_5%_4  [R0402]  175.43 80.84 0 bottom
PR2028  *Short_0402  [S0402]  178.86 76.55 90 bottom
PR2029  *0_5%_4  [R0402]  173.88 79.34 270 bottom
PR2030  *Short_0402  [S0402]  179.52 84.73 270 bottom
PR2031  *0_5%_4  [R0402]  178.56 84.27 270 bottom
PR2032  7.87K_1%_4  [R0402]  176.93 77.89 180 bottom
PR2033  10K_1%_4  [R0402]  175.2 77.89 0 bottom
PR3020  10K_5%_4  [R0402]  286.16 84.7 90 top
PR3021  24K_1%_4  [R0402]  287.78 80.41 180 top
PR3022  *Short_0402  [S0402]  290.57 80.99 90 top
PR6413  *Short_0805  [S0805]  38.59 65.32 90 top
PR9000  *EV@220K_NTC_4_5%  [R0402]  140.63 98.77 90 top
PR9001  *EV@10K_1%_4  [R0402]  139.01 74.01 180 top
PR9002  *EV@0_5%_4  [R0402]  148.1 71.85 180 top
PR9003  EV@100K_1%_4  [R0402]  145.21 73.42 90 top
PR9004  EV@12K_1%_4  [R0402]  139.01 73.04 0 top
PR9005  EV@100_1%_4  [R0402]  144.55 102.45 0 top
PR9006  EV@1K_1%_4  [R0402]  146.71 70.83 270 top
PR9007  EV@1M_5%_4  [R0402]  144.22 73.42 270 top
PR9008  *Short_0402  [S0402]  144.55 101.49 180 top
PR9009  *Short_0402  [S0402]  144.55 100.52 180 top
PR9010  EV@10K_1%_4  [R0402]  136.47 71.47 90 bottom
PR9011  *Short_0402  [S0402]  137.43 71.47 90 bottom
PR9012  EV@100_1%_4  [R0402]  144.55 99.53 0 top
PR9013  EV@18K_1%_4  [R0402]  144.34 62.58 270 bottom
PR9014  EV@15K_1%_4  [R0402]  146.07 62.58 270 bottom
PR9015  EV@10K_1%_4  [R0402]  141.47 62.6 270 bottom
PR9016  EV@21.5K_1%_4  [R0402]  137.51 68.9 180 top
PR9017  EV@1K_1%_4  [R0402]  137.54 67.89 180 bottom
PR9018  EV@10K_1%_4  [R0402]  136.8 73.37 0 bottom
PR9019  *EV@10K_1%_4  [R0402]  138.4 71.47 270 bottom
PR9020  *EV@2.4K_1%_4  [R0402]  137.54 66.92 0 bottom
PR9021  *EV@100K_1%_4  [R0402]  138.07 65.96 180 bottom
PR9022  *Short_0402  [S0402]  138.58 73.42 90 bottom
PR9023  EV@2.94K_1%_4  [R0402]  144.37 64.58 90 bottom
PR9024  EV@2.8K_1%_4  [R0402]  145.33 64.58 90 bottom
PR9025  *EV@8.2K_1%_4  [R0402]  141.47 64.74 90 bottom
PR9026  EV@18.7K_1%_4  [R0402]  137.51 69.87 0 top
PR9027  *EV@0_5%_4  [R0402]  136.34 65.96 180 bottom
PR9028  *Short_0402  [S0402]  135.76 64.61 270 bottom
PR9029  EV@6.19K_1%_4  [R0402]  139.54 73.42 90 bottom
PR9030  EV@20.5K_1%_4  [R0402]  140.51 73.42 90 bottom
PR9031  EV@4.32K_1%_4  [R0402]  141.85 73.8 180 bottom
PR9032  EV@90.9K_1%_4  [R0402]  142.44 64.56 90 top
PR9033  *Short_0402  [S0402]  139.97 64.48 180 bottom
PR9034  EV@2.4K_1%_4  [R0402]  138.07 64.02 0 bottom
PR9035  EV@10K_1%_4  [R0402]  143.43 64.56 270 top
PR9036  EV@309_1%_4  [R0402]  142.36 75.2 270 bottom
PR9037  EV@16.5K_1%_4  [R0402]  141.4 75.2 90 bottom
PR9038  *Short_0402  [S0402]  139.97 65.45 0 bottom
PR9039  EV@20.5K_1%_4  [R0402]  143.2 73.42 270 bottom
PR9040  EV@18.2K_1%_4  [R0402]  143.4 64.58 90 bottom
PR9041  *Short_0402  [S0402]  142.92 63.24 180 bottom
PR9042  *Short_0402  [S0402]  144.17 73.42 270 bottom
PR9043  EV@20K_1%_4  [R0402]  152.14 63.52 90 bottom
PR9044  *Short_0402  [S0402]  145.13 73.42 270 bottom
PR9045  *EV@165K_1%_4  [R0402]  150.39 64.35 180 bottom
PR9046  EV@20K_1%_4  [R0402]  153.11 62.91 90 bottom
PR9047  *Short_0402  [S0402]  146.1 73.42 270 bottom
PR9048  *EV@165K_1%_4  [R0402]  149.02 65.19 270 bottom
PR9049  EV@20K_1%_4  [R0402]  155.65 62.78 90 bottom
PR9050  EV@20K_1%_4  [R0402]  154.07 62.93 90 bottom
PR9051  *Short_0402  [S0402]  147.06 73.42 270 bottom
PR9052  *EV@75K_1%_4  [R0402]  150.36 65.65 180 bottom
PR9053  EV@2.2_5%_6  [R0603]  147.16 71.8 0 bottom
PR9054  *Short_0805  [S0805]  107.89 66.26 270 top
PR9055  *Short_0805  [S0805]  102.05 66.51 90 top
PR9056  *Short_0402  [S0402]  105.68 74.77 90 top
PR9057  *Short_0402  [S0402]  103.65 75.15 270 top
PR9058  EV@1_5%_6  [R0603]  157.42 65.07 270 bottom
PR9059  EV@5.6_5%_8  [R0805]  153.87 60.52 90 top
PR9060  EV@1_5%_6  [R0603]  153.79 65.12 270 bottom
PR9061  EV@100K_1%_4  [R0402]  148.64 58.16 270 top
PR9062  EV@1M_5%_4  [R0402]  150.29 56.71 180 top
PR9063  EV@10K_1%_4  [R0402]  155.21 58.08 180 top
PR9064  EV@47_1%_4  [R0402]  161.11 61.64 180 bottom
PR9065  *Short_0402  [S0402]  164.89 59.5 90 bottom
PR9066  EV@100_1%_4  [R0402]  161.13 58.06 180 bottom
PR9067  EV@100_1%_4  [R0402]  161.13 59.07 0 bottom
PR9068  EV@3.3_5%_6  [R0603]  129.69 93.69 0 top
PR9069  *Short_0402  [S0402]  132.61 98.9 90 top
PR9070  *Short_0402  [S0402]  130.25 96.87 0 top
PR9071  *Short_0402  [S0402]  130.25 95.9 180 top
PR9072  *EV@0_5%_4  [R0402]  130.25 94.94 0 top
PR9073  *EV@2.2_5%_6  [R0603]  139.67 92.37 270 bottom
PR9074  *Short_0201  [S0201]  142.26 92.42 0 top
PR9075  *Short_0201  [S0201]  147.59 92.42 180 top
PR9077  *Short_0402  [S0402]  156.96 58.08 0 top
PR9119  EV@1_5%_6  [R0603]  111.4 78.58 270 top
PR9121  EV@10K_1%_4  [R0402]  120.92 75.81 90 top
PR9122  *EV@2.2_5%_6  [R0603]  108.73 86.88 0 bottom
PR9123  EV@15K_1%_4  [R0402]  111.27 76.67 0 top
PR9124  EV@12K_1%_4  [R0402]  111.25 74.64 180 top
PR9126  *EV@10K_1%_4  [R0402]  111.25 71.75 180 top
PR9128  EV@30.9K_1%_4  [R0402]  112.8 72.33 270 top
PR9129  EV@10K_1%_4  [R0402]  114.17 72.36 270 top
PR9131  EV@69.8K_1%_4  [R0402]  113.81 70.78 0 top
PR9132  EV@100K_1%_4  [R0402]  113.13 67.66 270 top
PR9135  *Short_0402  [S0402]  118.99 72.36 90 top
PR9136  EV@100_1%_4  [R0402]  120.34 73.47 0 top
PR9138  *Short_0402  [S0402]  120.34 74.44 180 top
PR9139  *EV@100K_1%_4  [R0402]  109.47 71.75 180 top
PR9140  EV@1M_5%_4  [R0402]  113.13 69.43 270 top
PR9141  EV@75K_1%_4  [R0402]  109.47 72.71 180 top
PR9142  EV@1_5%_6  [R0603]  119.6 70.07 270 top
PR9145  EV@402K_1%_4  [R0402]  117.06 72.36 90 top
PR9147  EV@86.6K_1%_4  [R0402]  118.99 75.81 270 top
PR9165  EV@10K_1%_4  [R0402]  148.98 61.48 180 top
PR9208  EV@22_5%_8  [R0805]  105.81 76.75 0 top
PR9209  EV@100K_1%_4  [R0402]  102.89 77.18 180 bottom
PR9210  EV@1M_5%_4  [R0402]  102.89 78.2 0 bottom
PR9215  EV@1_5%_6  [R0603]  117.01 75.48 270 bottom
PR9217  *Short_0402  [S0402]  120.95 77.59 90 top
PR9223  *Short_0402  [S0402]  104.67 74.77 270 top
PR9224  *EV@0_5%_4  [R0402]  111.25 73.68 0 top
PR9225  *Short_0805  [S0805]  107.16 73.96 90 top
PR9226  *Short_0805  [S0805]  102.15 73.98 90 top
PR9227  22_5%_8  [R0805]  110.51 64.35 0 top
PR9229  *VL@0_5%_4  [R0402]  363.99 88.15 180 top
PR9230  *Short_0201  [S0201]  369.81 85.33 270 top
PR9231  VL@174K_1%_4  [R0402]  366.36 82.32 180 top
PR9232  VL@20K_1%_4  [R0402]  364.63 82.33 180 top
PR9233  VL@100K_5%_4  [R0402]  363.17 83.16 90 top
PR9234  *Short_0402  [S0402]  365.72 88.15 180 top
PR9235  EV@2K_1%_4  [R0402]  146.71 66.74 0 bottom
PR9236  EV@100K_1%_4  [R0402]  137.51 67.94 180 top
PR9237  *EV@100K_1%_4  [R0402]  148.05 69.94 90 bottom
PR9238  EV@1_5%_6  [R0603]  155.6 65.17 270 bottom
PR9239  EV@2K_1%_4  [R0402]  146.71 67.71 0 bottom
PR9240  EV@1K_1%_4  [R0402]  146.71 65.78 0 bottom
PR9241  *Short_0402  [S0402]  136.16 67.38 270 top
PR9242  EV@1_5%_6  [R0603]  152.32 65.75 270 bottom
PR9243  EV@2K_1%_4  [R0402]  146.71 68.67 0 bottom
PR9244  EV@100K_1%_4  [R0402]  137.51 66.97 180 top
PR9245  EV@2K_1%_4  [R0402]  146.71 69.64 0 bottom
PR9256  *Short_0402  [S0402]  133.62 98.9 90 top
PR66825  *Short_0201  [S0201]  261.23 163.06 180 top
PR66826  *Short_0201  [S0201]  261.23 163.77 180 top
PR66827  *Short_0201  [S0201]  261.23 164.48 180 top
PR66832  10K_1%_2  [R0201]  262.99 168.47 270 bottom
PR66835  *Short_0201  [S0201]  261.23 165.19 180 top
PR66836  *Short_0201  [S0201]  261.23 165.9 180 top
PR66837  *Short_0402  [S0402]  270.07 168.85 270 top
PR66838  4.7_1%_6  [R0603]  261.13 164.05 270 bottom
PR66839  *Short_0201  [S0201]  261.23 166.62 180 top
PR66840  2M_1%_4  [R0402]  260.37 160.09 270 top
PR66841  *Short_0201  [S0201]  266.26 158.74 0 bottom
PR66842  133K_1%_4  [R0402]  261.34 160.06 270 top
PR66843  *Short_0201  [S0201]  265.27 158.74 0 bottom
PR66844  *Short_0201  [S0201]  264.28 158.77 0 bottom
PR66845  *Short_0201  [S0201]  263.29 158.77 180 bottom
PR66846  *Short_0201  [S0201]  262.3 158.77 180 bottom
PR66847  *Short_0201  [S0201]  260.5 158.67 270 top
PR66848  *Short_0201  [S0201]  260.67 167.48 270 top
PR66849  *Short_0201  [S0201]  262.99 168.47 270 top
PR66850  *Short_0201  [S0201]  265.12 168.47 270 top
PR66851  10K_1%_4  [R0402]  267.08 169.94 270 top
PR66852  1.5K_1%_4  [R0402]  263.29 158.33 270 top
PR66853  *Short_0201  [S0201]  266.54 168.47 270 top
PR66854  *Short_0201  [S0201]  263.7 168.47 90 top
PR66855  1.5K_1%_4  [R0402]  266.26 158.31 90 top
PR66856  *Short_0201  [S0201]  264.41 168.47 270 top
PR66857  1.5K_1%_4  [R0402]  265.27 158.31 270 top
PR66858  1.5K_1%_4  [R0402]  264.28 158.33 90 top
PR66860  1.5K_1%_4  [R0402]  262.3 158.33 90 top
PR66861  *Short_0201  [S0201]  267.28 168.47 270 top
PR66862  1.5K_1%_4  [R0402]  261.34 158.31 270 top
PR66863  10_1%_4  [R0402]  268.14 168.85 90 top
PR66864  1.43K_1%_4  [R0402]  266.31 160.49 180 bottom
PR66865  49.9_1%_2  [R0201]  269.11 168.85 270 top
PR66866  *0_5%_2  [R0201]  272.08 168.62 180 top
PR66867  *0_5%_2  [R0201]  267.53 160.49 270 bottom
PR66868  100_1%_2  [R0201]  248.05 139.08 180 bottom
PR66869  *0_5%_2  [R0201]  259.3 161.59 0 top
PR66870  *Short_0201  [S0201]  272.08 167.91 180 top
PR66871  20K_1%_4  [R0402]  260.34 161.81 90 top
PR66872  *Short_0201  [S0201]  267.2 158.64 270 top
PR66874  *Short_0201  [S0201]  267.91 158.64 270 top
PR66875  61.9K_1%_4  [R0402]  271.98 167.05 0 top
PR66876  2.1K_1%_4  [R0402]  269.16 158.64 180 top
PR66877  *Short_0201  [S0201]  271.62 162.83 180 top
